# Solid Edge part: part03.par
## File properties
Author: Administrator
Template: normal.par
Last saved by: Cadcim
Revision: 11
Application: Solid Edge
Accuracy: 0.99
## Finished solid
Body 1: solid body, 54 faces, 136 edges, 72 vertices.
  Faces by surface: cylinder 40, plane 14
  Edges by curve: circle 74, line 50, ellipse 12
Bounding box of the edges (mm): 320.500 x 112.000 x 70.000, from (-118.4884, -56, -35) to (202.0116, 56, 35).
Cylindrical faces by radius (mm): R5 x8, R6 x2, R12 x1, R13 x8, R17.5 x1, R26 x1, R31.5 x3, R35 x2, R72.03 x8, R78 x4, R207.0766 x1, R207.2725 x1
Planar faces by outward normal: +y 1, +z 4, -y 1, -z 4, oblique 4
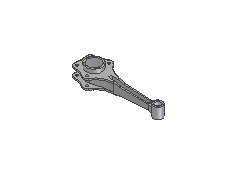
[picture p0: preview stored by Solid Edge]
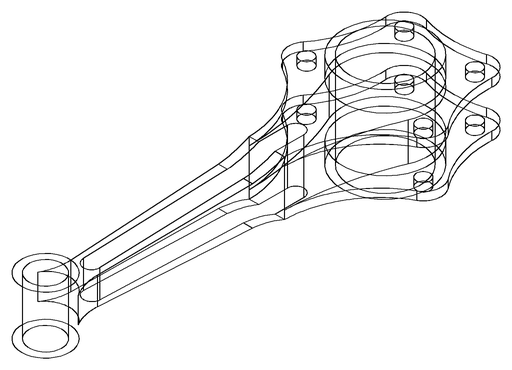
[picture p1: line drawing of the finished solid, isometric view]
